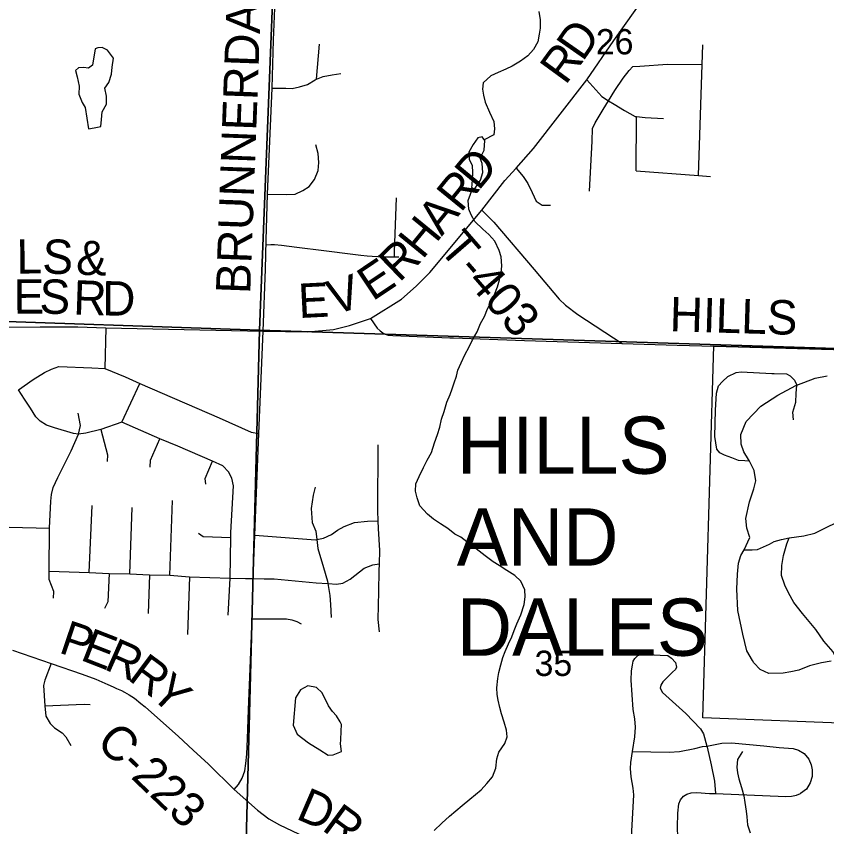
# Model space of a CAD drawing. Extents: x 0 to 34, y 0 to 22.
# Drawn here: x 6.833 to 8.174, y 15.034 to 16.375 of the extents above; entities that cross this region are included whole.
import ezdxf

# ---------------------------------------------------------------- set-up
doc = ezdxf.new("R2010")
doc.units = 0
for name, color, linetype in [('GM_X_City_Street', 7, 'Continuous'), ('GM_X_Corporation', 7, 'Continuous'), ('GM_X_Corporation_Text', 7, 'Continuous'), ('GM_X_County_Road', 7, 'Continuous'), ('GM_X_County_Road_Text', 7, 'Continuous'), ('GM_X_Minor_Lake', 7, 'Continuous'), ('GM_X_Minor_River', 7, 'Continuous'), ('GM_X_Section_Text', 7, 'Continuous'), ('GM_X_Township_Road', 7, 'Continuous'), ('GM_X_Township_Road_Text', 7, 'Continuous')]:
    doc.layers.add(name, color=color, linetype=linetype)

msp = doc.modelspace()

# ---------------------------------------------------------------- linework, layer by layer
at = {"layer": 'GM_X_City_Street'}
for points in [[(8.0459, 15.6389), (8.038, 15.6393), (8.0278, 15.6401), (8.0167, 15.6444), (8.0044, 15.6491), (7.9966, 15.6529), (7.9915, 15.6588), (7.9883, 15.6799), (7.9894, 15.7235), (7.991, 15.7516), (7.9946, 15.7636), (8.0009, 15.7709), (8.01, 15.7789), (8.0236, 15.7855), (8.032, 15.787), (8.0825, 15.7841), (8.0864, 15.7839), (8.1072, 15.7833), (8.1132, 15.78), (8.1201, 15.7729), (8.1242, 15.7647)], [(8.1809, 15.3084), (8.1649, 15.3057), (8.145, 15.3008), (8.1272, 15.2933), (8.1142, 15.2904), (8.1012, 15.2883), (8.0777, 15.2878), (8.0632, 15.2946), (8.0531, 15.3053), (8.0506, 15.3096), (8.0414, 15.3252), (8.0347, 15.3528), (8.0265, 15.392), (8.0246, 15.4274), (8.0257, 15.4521), (8.0273, 15.4706), (8.0316, 15.483), (8.037, 15.4922), (8.0462, 15.5127), (8.0415, 15.5281), (8.0396, 15.5442), (8.0457, 15.572), (8.0527, 15.5934), (8.0563, 15.6065), (8.0537, 15.6238), (8.0459, 15.6389), (8.0442, 15.642), (8.0361, 15.6546), (8.0317, 15.6673), (8.0316, 15.6833), (8.0401, 15.7046), (8.0644, 15.7301), (8.0924, 15.7479), (8.1223, 15.764), (8.1242, 15.7647), (8.1543, 15.7763), (8.1742, 15.78)], [(8.1187, 15.7072), (8.1174, 15.7202), (8.1223, 15.7363), (8.1229, 15.7507), (8.1242, 15.7647)], [(8.037, 15.4922), (8.0502, 15.4924), (8.059, 15.4932), (8.0787, 15.5018), (8.0865, 15.5064), (8.0987, 15.5097), (8.1116, 15.5122), (8.1354, 15.5153), (8.1538, 15.5201), (8.1724, 15.5292), (8.1898, 15.5376), (8.2112, 15.5553)], [(8.191, 15.3087), (8.1839, 15.3235), (8.1687, 15.3416), (8.1552, 15.3608), (8.1332, 15.3873), (8.1192, 15.4054), (8.11, 15.421), (8.1042, 15.4342), (8.0984, 15.45), (8.0991, 15.4663), (8.1021, 15.4829), (8.1075, 15.5024), (8.1116, 15.5122)]]:
    msp.add_lwpolyline(points, dxfattribs=at)
at = {"layer": 'GM_X_Corporation'}
for points in [[(6.2453, 16.9071), (7.2756, 16.8704), (7.2356, 15.8559), (6.2042, 15.8911)], [(7.2756, 16.8704), (8.2669, 16.8377), (8.2409, 15.8234), (7.2356, 15.8559)], [(6.2042, 15.8911), (7.2356, 15.8559), (7.2089, 14.8416), (6.1854, 14.88)], [(8.2409, 15.8234), (8.2165, 14.8042), (7.2089, 14.8416), (7.2356, 15.8559)], [(8.2307, 15.8231), (8.4926, 15.8129), (8.475, 15.3073), (8.3547, 15.3061), (8.3504, 15.0484), (8.219, 15.0514), (8.2237, 15.2046), (7.9685, 15.2144), (7.9869, 15.8297)]]:
    msp.add_lwpolyline(points, close=True, dxfattribs=at)
at = {"layer": 'GM_X_County_Road'}
msp.add_line((7.1108, 15.8568), (7.2413, 15.8538), dxfattribs=at)
for points in [[(7.2413, 15.8538), (7.3149, 15.8528), (7.3578, 15.857), (7.3843, 15.8636), (7.4187, 15.8751), (7.47, 15.907), (7.4947, 15.9282), (7.517, 15.9511), (7.6033, 16.0542), (7.6412, 16.1034), (7.66, 16.1236), (7.6884, 16.1562), (7.777, 16.2696), (7.8215, 16.3345), (7.8745, 16.4095)], [(7.4187, 15.8751), (7.4302, 15.8588), (7.4352, 15.8548), (7.4416, 15.8497), (7.4483, 15.8476), (7.4561, 15.8467), (7.5502, 15.8431), (7.5562, 15.8429)], [(6.7654, 15.8605), (6.8727, 15.8614), (6.935, 15.8613), (6.9812, 15.8597), (7.1108, 15.8568)], [(7.5562, 15.8429), (7.6739, 15.8383), (7.8349, 15.8334), (7.926, 15.8309)], [(7.926, 15.8309), (7.9871, 15.8292), (8.2239, 15.8224), (8.4358, 15.8145)], [(6.8267, 15.3266), (6.891, 15.3044), (6.9423, 15.2868), (6.9646, 15.2784), (6.9847, 15.2698), (6.9933, 15.2659), (6.9988, 15.2633), (7.007, 15.2595), (7.0123, 15.2568), (7.0199, 15.2524), (7.0286, 15.2469), (7.0394, 15.2385), (7.0462, 15.2327), (7.1014, 15.1835), (7.1259, 15.1611), (7.1513, 15.1377), (7.1936, 15.0963)], [(7.1936, 15.0963), (7.2319, 15.0616), (7.2511, 15.0473), (7.2683, 15.0378), (7.3304, 15.0085), (7.3429, 15.0015), (7.3507, 14.9963), (7.3573, 14.9907), (7.3641, 14.9839), (7.3725, 14.9743), (7.3858, 14.9564), (7.4178, 14.9119), (7.4463, 14.8734), (7.4603, 14.8581), (7.4891, 14.8288), (7.5219, 14.7964), (7.556, 14.7627)]]:
    msp.add_lwpolyline(points, dxfattribs=at)
at = {"layer": 'GM_X_Minor_Lake'}
for points in [[(6.9527, 16.1884), (6.9618, 16.1901), (6.9732, 16.1925), (6.9742, 16.2039), (6.9751, 16.2169), (6.9825, 16.2295), (6.9824, 16.2424), (6.9795, 16.2561), (6.9862, 16.2653), (6.9906, 16.279), (6.9916, 16.2908), (6.994, 16.3057), (6.984, 16.3184), (6.9752, 16.3229), (6.968, 16.3228), (6.9635, 16.3208), (6.9593, 16.2941), (6.9525, 16.2891), (6.9445, 16.2898), (6.9358, 16.2893), (6.931, 16.285), (6.9341, 16.2744), (6.937, 16.2593), (6.9364, 16.246), (6.9419, 16.232), (6.9473, 16.2237)], [(6.9473, 16.2237), (6.9527, 16.1884)], [(7.591, 16.0887), (7.6011, 16.1037), (7.6047, 16.1163), (7.6034, 16.1315), (7.6002, 16.1402), (7.6072, 16.1532), (7.6082, 16.1691), (7.6035, 16.1752), (7.5967, 16.1735), (7.5889, 16.1628), (7.5815, 16.1501), (7.5824, 16.1376), (7.5871, 16.1286), (7.5876, 16.116)], [(7.5876, 16.116), (7.5864, 16.0956), (7.5858, 16.0923), (7.591, 16.0887)], [(7.3686, 15.2079), (7.3627, 15.2177), (7.3562, 15.2252), (7.3496, 15.2343), (7.3391, 15.2558), (7.3298, 15.2648), (7.3154, 15.2676), (7.3033, 15.261), (7.2948, 15.2479), (7.2912, 15.2027), (7.2979, 15.1876), (7.3167, 15.173), (7.3354, 15.1615), (7.3492, 15.1526), (7.3572, 15.1531), (7.3711, 15.159)], [(7.3711, 15.159), (7.3696, 15.1716), (7.3698, 15.1784), (7.3705, 15.1926), (7.371, 15.2033), (7.3686, 15.2079)]]:
    msp.add_lwpolyline(points, dxfattribs=at)
at = {"layer": 'GM_X_Minor_River'}
for points in [[(7.6971, 16.3828), (7.6995, 16.3688), (7.6993, 16.3551), (7.698, 16.3452), (7.6955, 16.3326), (7.6888, 16.3196), (7.6791, 16.3092), (7.6671, 16.3003), (7.6531, 16.2921), (7.6426, 16.2874), (7.6302, 16.2815), (7.6177, 16.276), (7.6053, 16.2645), (7.6043, 16.2542), (7.6056, 16.2443), (7.6088, 16.2326), (7.6159, 16.216), (7.6229, 16.2009), (7.6242, 16.1884), (7.6232, 16.1789), (7.6071, 16.1705)], [(7.6302, 15.2435), (7.6282, 15.2534), (7.628, 15.2644), (7.6297, 15.2796), (7.6311, 15.2895), (7.6347, 15.3021), (7.6376, 15.3143), (7.6416, 15.3242), (7.6471, 15.3372), (7.6527, 15.3487), (7.6567, 15.359), (7.6611, 15.3701), (7.6674, 15.385), (7.6732, 15.4018), (7.6745, 15.4144), (7.6744, 15.4261), (7.6674, 15.4405), (7.6574, 15.4498), (7.6447, 15.458), (7.6317, 15.4662), (7.6218, 15.4725), (7.6087, 15.4826), (7.5938, 15.4938), (7.5781, 15.5057), (7.5685, 15.5132), (7.5586, 15.5184), (7.5471, 15.5277), (7.5348, 15.5355), (7.5233, 15.5433), (7.5134, 15.5512), (7.5006, 15.5654), (7.4963, 15.5783), (7.4935, 15.5893), (7.4941, 15.6014), (7.4992, 15.6137), (7.5066, 15.6286), (7.5129, 15.6404), (7.5196, 15.6535), (7.5247, 15.6691), (7.5298, 15.6829), (7.5334, 15.6954), (7.5366, 15.7084), (7.541, 15.7214), (7.5454, 15.7363), (7.5505, 15.7493), (7.5542, 15.7588), (7.5575, 15.7683), (7.5611, 15.7794), (7.5632, 15.7897), (7.5688, 15.8016), (7.5747, 15.8146), (7.5824, 15.828), (7.5876, 15.8394), (7.5954, 15.8528), (7.6009, 15.8666), (7.6076, 15.8785), (7.6127, 15.8907), (7.6193, 15.9037), (7.6241, 15.9148), (7.6289, 15.9274), (7.6321, 15.9389), (7.635, 15.9503), (7.6364, 15.9621), (7.635, 15.9769), (7.6319, 15.9875), (7.6245, 16.0026), (7.6148, 16.0138), (7.6045, 16.0224), (7.5914, 16.0352), (7.5855, 16.0461), (7.5816, 16.0559), (7.5803, 16.07), (7.588, 16.0908)], [(7.5242, 15.0281), (7.537, 15.0401), (7.5497, 15.0517), (7.5707, 15.0694), (7.5835, 15.0802), (7.6019, 15.0953), (7.6116, 15.1057), (7.6205, 15.1172), (7.6264, 15.1314), (7.6277, 15.1466), (7.631, 15.158), (7.641, 15.1719), (7.6451, 15.1829), (7.6438, 15.1943), (7.6402, 15.2076), (7.6358, 15.2212), (7.633, 15.2318), (7.6302, 15.2435)], [(8.0342, 15.1591), (8.0261, 15.1457), (8.0247, 15.1332), (8.026, 15.1237), (8.028, 15.1135), (8.0324, 15.0991), (8.0364, 15.0858), (8.038, 15.0748), (8.0401, 15.0604), (8.0414, 15.051), (8.0427, 15.0377), (8.0471, 15.0244)]]:
    msp.add_lwpolyline(points, dxfattribs=at)
at = {"layer": 'GM_X_Township_Road'}
for p, q in [((7.3297, 16.2705), (7.3344, 16.3284)), ((7.8581, 16.1191), (7.8591, 16.2088)), ((6.9812, 15.8597), (6.9794, 15.792)), ((7.0076, 15.7037), (7.0376, 15.7673)), ((6.9538, 15.4548), (6.9586, 15.5658)), ((7.0871, 15.4503), (7.0916, 15.5737)), ((7.0207, 15.4527), (7.0246, 15.5622)), ((7.0533, 15.4509), (7.0512, 15.3873)), ((7.1199, 15.4476), (7.1166, 15.3523))]:
    msp.add_line(p, q, dxfattribs=at)
for points in [[(7.2467, 16.0045), (7.2485, 16.0807), (7.2561, 16.2561), (7.2586, 16.3351), (7.2628, 16.4414), (7.2702, 16.6492), (7.2725, 16.7309), (7.2758, 16.8058), (7.2764, 16.8421), (7.2803, 16.9391), (7.293, 17.3173)], [(7.9613, 16.1114), (7.9677, 16.2948), (7.9688, 16.3274)], [(7.781, 16.0853), (7.7853, 16.1684), (7.7859, 16.1889), (7.7905, 16.1983), (7.804, 16.2205), (7.8128, 16.235), (7.8232, 16.2518), (7.837, 16.2726), (7.847, 16.285), (7.8527, 16.2914), (7.8645, 16.292), (7.9099, 16.2954), (7.9677, 16.2948)], [(7.2561, 16.2561), (7.2789, 16.2556), (7.2895, 16.2555), (7.3017, 16.2582), (7.3148, 16.2618), (7.3277, 16.2697), (7.3297, 16.2705), (7.3406, 16.2749), (7.3558, 16.2781), (7.3698, 16.2803)], [(7.777, 16.2696), (7.8016, 16.2418), (7.8128, 16.235), (7.8218, 16.2295), (7.8391, 16.2191), (7.8568, 16.209), (7.8591, 16.2088), (7.873, 16.2073), (7.9036, 16.2059)], [(7.2485, 16.0807), (7.2803, 16.0801), (7.2942, 16.0807), (7.3071, 16.0867), (7.3174, 16.0933), (7.3264, 16.1046), (7.3323, 16.1195), (7.3333, 16.1328), (7.3323, 16.1477), (7.3283, 16.1623)], [(7.66, 16.1236), (7.6715, 16.1097), (7.6793, 16.0983), (7.6865, 16.0832), (7.6932, 16.0687), (7.7028, 16.0621), (7.7167, 16.0621)], [(7.8581, 16.1191), (7.9613, 16.1114), (7.9813, 16.1099)], [(7.4587, 15.977), (7.4588, 15.985), (7.4621, 16.0743)], [(7.6033, 16.0542), (7.6232, 16.0343), (7.6896, 15.9559), (7.7312, 15.907), (7.7414, 15.8968), (7.762, 15.8817), (7.8349, 15.8334)], [(7.2413, 15.8538), (7.2456, 15.9564), (7.2467, 16.0045)], [(7.2466, 15.9966), (7.2541, 15.9972), (7.2603, 15.9972), (7.2718, 15.9962), (7.2972, 15.9929), (7.3416, 15.9876), (7.3595, 15.9851), (7.3721, 15.9837), (7.3854, 15.9818), (7.3942, 15.9808), (7.4029, 15.9798), (7.4136, 15.9788), (7.4216, 15.978), (7.4313, 15.9772), (7.4366, 15.9771), (7.4507, 15.977), (7.4587, 15.977), (7.4661, 15.9771)], [(7.1936, 15.0963), (7.2005, 15.1042), (7.2069, 15.1149), (7.211, 15.127), (7.2129, 15.1393), (7.2144, 15.1542), (7.2156, 15.1796), (7.2174, 15.228), (7.223, 15.378), (7.2249, 15.4449), (7.2279, 15.5167), (7.2342, 15.6847), (7.2413, 15.8538)], [(7.0076, 15.7037), (6.9728, 15.6916), (6.948, 15.6854), (6.9363, 15.6838), (6.9278, 15.6847), (6.8964, 15.6943), (6.8829, 15.6988), (6.8729, 15.7052), (6.8657, 15.7124), (6.8566, 15.7269), (6.8467, 15.7414), (6.8367, 15.7568), (6.8609, 15.7739), (6.8796, 15.7857), (6.8913, 15.7914), (6.9034, 15.7954), (6.958, 15.7935), (6.9794, 15.792), (7.0135, 15.7782), (7.0376, 15.7673), (7.1685, 15.7106), (7.2216, 15.6868), (7.2342, 15.6847)], [(6.8949, 15.4126), (6.8952, 15.4232), (6.8874, 15.4434), (6.8877, 15.457), (6.8882, 15.5284), (6.8901, 15.5728), (6.8915, 15.5841), (6.8943, 15.5952), (6.9019, 15.612), (6.9237, 15.656), (6.9363, 15.6838), (6.9396, 15.6982), (6.9357, 15.7184)], [(7.1838, 15.3842), (7.1868, 15.4457), (7.1878, 15.5125), (7.188, 15.5212), (7.1923, 15.5984), (7.1899, 15.6111), (7.1842, 15.6216), (7.1745, 15.6313), (7.1576, 15.6388), (7.1002, 15.664), (7.0705, 15.6762), (7.0076, 15.7037)], [(6.9728, 15.6916), (6.9842, 15.6494), (6.9833, 15.6382)], [(7.0548, 15.6289), (7.0551, 15.6409), (7.0705, 15.6762)], [(7.431, 15.666), (7.4304, 15.5566), (7.4312, 15.5403), (7.4318, 15.5278), (7.4339, 15.491), (7.4332, 15.4691), (7.4329, 15.4575), (7.4322, 15.4237), (7.4312, 15.3774), (7.4331, 15.3565)], [(7.1468, 15.6008), (7.1456, 15.6105), (7.1576, 15.6388)], [(7.3276, 15.5961), (7.3239, 15.5827), (7.3206, 15.5609), (7.3225, 15.5378), (7.3287, 15.5232), (7.3302, 15.5092), (7.3316, 15.4945), (7.3415, 15.4629), (7.3476, 15.4404), (7.3482, 15.4369), (7.3515, 15.417), (7.3528, 15.4022), (7.3539, 15.3806)], [(7.2279, 15.5167), (7.3281, 15.5088), (7.3302, 15.5092), (7.3413, 15.5114), (7.3546, 15.5177), (7.3645, 15.5248), (7.3752, 15.5311), (7.3923, 15.5374), (7.4142, 15.5399), (7.4312, 15.5403)], [(6.5348, 15.4894), (6.5752, 15.4995), (6.6592, 15.5241), (6.6721, 15.5258), (6.6872, 15.5264), (6.7172, 15.5257), (6.7304, 15.5256), (6.7384, 15.5268), (6.7496, 15.5307), (6.7562, 15.5316), (6.7956, 15.5311), (6.8213, 15.5301), (6.8882, 15.5284)], [(7.1344, 15.5197), (7.142, 15.5146), (7.1878, 15.5125)], [(6.8877, 15.457), (6.9538, 15.4548), (6.9869, 15.453), (7.0207, 15.4527), (7.0533, 15.4509), (7.0871, 15.4503), (7.1199, 15.4476), (7.1868, 15.4457), (7.2122, 15.4452)], [(7.2122, 15.4452), (7.2249, 15.4449), (7.2433, 15.4443), (7.2596, 15.4446), (7.3289, 15.4379), (7.3482, 15.4369), (7.3489, 15.4369), (7.3629, 15.4356), (7.3731, 15.437), (7.3856, 15.4441), (7.4085, 15.4621), (7.4226, 15.4677), (7.4332, 15.4691)], [(6.9869, 15.453), (6.9848, 15.4066), (6.9791, 15.3951)], [(7.223, 15.378), (7.28, 15.378), (7.2888, 15.3767), (7.2974, 15.3736), (7.3044, 15.3698)], [(7.845, 14.9175), (7.8542, 15.0872), (7.8535, 15.0982), (7.8503, 15.1171), (7.849, 15.1307), (7.8494, 15.1406), (7.8522, 15.1591), (7.8559, 15.183), (7.857, 15.1991), (7.8559, 15.2131), (7.8535, 15.2286), (7.8503, 15.277), (7.8507, 15.2925), (7.852, 15.3019), (7.8535, 15.3084), (7.8561, 15.3129), (7.8613, 15.3179), (7.8675, 15.3198), (7.8978, 15.3182), (7.9105, 15.3174), (7.917, 15.3135), (7.9236, 15.306), (7.9252, 15.2982), (7.9235, 15.2943), (7.9185, 15.2901), (7.9024, 15.274), (7.8989, 15.2686), (7.8978, 15.2636), (7.9021, 15.2563), (7.9404, 15.2215), (7.9647, 15.1961), (7.9695, 15.1883), (7.9751, 15.1679), (7.9756, 15.1658)], [(6.891, 15.3044), (6.8802, 15.2769), (6.8784, 15.2681), (6.8802, 15.2344), (6.8823, 15.2175), (6.8892, 15.2051), (6.8964, 15.1979), (6.9088, 15.19), (6.9152, 15.1831), (6.9236, 15.1686)], [(6.8802, 15.2344), (6.9456, 15.2374), (6.9556, 15.2365)], [(7.8522, 15.1591), (7.9131, 15.1578), (7.9299, 15.1591), (7.9551, 15.1638), (7.9682, 15.167), (7.9751, 15.1679), (8.0002, 15.1729), (8.016, 15.1733), (8.0695, 15.1681), (8.0947, 15.1655), (8.1177, 15.1636), (8.1265, 15.1612), (8.1362, 15.1554), (8.144, 15.1462), (8.1476, 15.1371), (8.1493, 15.1283), (8.1491, 15.1176), (8.1461, 15.1072), (8.1401, 15.0967), (8.13, 15.0894)], [(7.9756, 15.1658), (7.9822, 15.1371), (7.9878, 15.1098), (7.9893, 15.0894)], [(7.9367, 14.8642), (7.9441, 14.885), (7.9471, 14.8997), (7.9461, 14.9126), (7.9367, 14.9431), (7.9318, 14.9579), (7.9279, 14.989), (7.9271, 15.0172), (7.9269, 15.0335), (7.9272, 15.057), (7.929, 15.0726), (7.9318, 15.0788), (7.9366, 15.0849), (7.9422, 15.0885), (7.949, 15.0905), (7.9585, 15.0909), (7.9794, 15.0892), (7.9893, 15.0894), (8.1057, 15.0846), (8.1151, 15.0849), (8.1235, 15.0866), (8.13, 15.0894)]]:
    msp.add_lwpolyline(points, dxfattribs=at)

# ---------------------------------------------------------------- texts
at = {"layer": 'GM_X_Corporation_Text'}
for s, p in [('HILLS', (7.5617, 15.6181)), ('AND', (7.5617, 15.4663)), ('DALES', (7.5617, 15.3172))]:
    msp.add_text(s, height=0.0947, rotation=0, dxfattribs=at).set_placement(p)
at = {"layer": 'GM_X_County_Road_Text'}
for s, height, rotation, p in [('D', 0.0568, 55.1235, (7.7698, 16.2983)), ('R', 0.0568, 53.8194, (7.7414, 16.2595)), ('D', 0.0568, 50.4743, (7.5976, 16.0848)), ('R', 0.0568, 50.8526, (7.5682, 16.0487)), ('A', 0.0568, 50.8557, (7.5367, 16.0099)), ('H', 0.0568, 50.7271, (7.5049, 15.9711)), ('L', 0.0568, 0.6729, (6.8339, 15.9491)), ('S', 0.0568, 358.0182, (6.8757, 15.9496)), ('&', 0.0568, 357.9669, (6.9316, 15.9476)), ('R', 0.0568, 44.0157, (7.4665, 15.9333)), ('E', 0.0568, 33.7549, (7.4225, 15.9027)), ('E', 0.0568, 0.3429, (6.829, 15.8829)), ('S', 0.0568, 358.717, (6.8711, 15.8832)), ('V', 0.0568, 16.9338, (7.3582, 15.8804)), ('R', 0.0568, 358.0411, (6.9269, 15.8817)), ('D', 0.0568, 359.4819, (6.9751, 15.88)), ('E', 0.0568, 2.8812, (7.3008, 15.8756)), ('HILLS', 0.05682, 358.3081, (7.9132, 15.854)), ('P', 0.0568, 341.2856, (6.9017, 15.323)), ('E', 0.0568, 338.6785, (6.9373, 15.311)), ('R', 0.0568, 336.1695, (6.9763, 15.2958)), ('R', 0.0568, 323.3167, (7.0161, 15.2786)), ('Y', 0.0568, 316.9297, (7.0522, 15.2518)), ('C-223', 0.05682, 316.3593, (6.9632, 15.1713)), ('D', 0.0568, 336.5627, (7.2939, 15.0484)), ('R', 0.0568, 323.5821, (7.3368, 15.0302))]:
    msp.add_text(s, height=height, rotation=rotation, dxfattribs=at).set_placement(p)
at = {"layer": 'GM_X_Section_Text'}
for s, p in [('26', (7.7916, 16.3117)), ('35', (7.6903, 15.2838))]:
    msp.add_text(s, height=0.04186, rotation=0, dxfattribs=at).set_placement(p)
at = {"layer": 'GM_X_Township_Road_Text'}
for s, height, rotation, p in [('BRUNNERDALE', 0.056818, 87.8791, (7.22, 15.9149)), ('T-403', 0.05682, 310.9014, (7.5303, 15.9896))]:
    msp.add_text(s, height=height, rotation=rotation, dxfattribs=at).set_placement(p)

doc.saveas('drawing.dxf')
